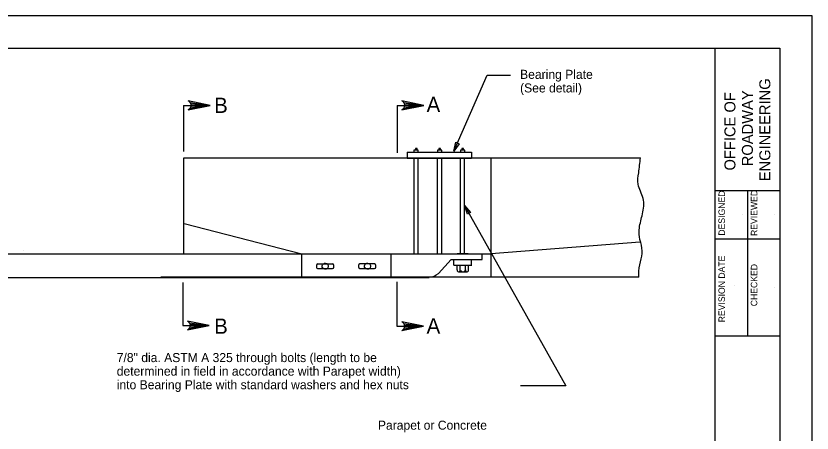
# Model space of a CAD drawing. Extents: x 0 to 34, y 0 to 22.
# Drawn here: x 21.69 to 34, y 15.55 to 22 of the extents above; entities that cross this region are included whole.
import ezdxf

# ---------------------------------------------------------------- set-up
doc = ezdxf.new("R2010")
doc.units = 0
for name, color, linetype in [('SH_Border', 7, 'Continuous'), ('SH_Cut_Line', 7, 'Continuous'), ('SH_Data', 7, 'Continuous'), ('ST_Details', 7, 'Continuous'), ('ST_Text', 7, 'Continuous')]:
    doc.layers.add(name, color=color, linetype=linetype)

msp = doc.modelspace()

# ---------------------------------------------------------------- linework, layer by layer
at = {"layer": 'SH_Border'}
for p, q in [((32.5, 0.5), (32.5, 21.5)), ((32.5, 19.3), (33.5, 19.3)), ((33, 19.3), (33, 17.05)), ((32.5, 18.55), (33.5, 18.55)), ((32.5, 17.05), (33.5, 17.05))]:
    msp.add_line(p, q, dxfattribs=at)
msp.add_lwpolyline([(2, 21.5), (33.5, 21.5), (33.5, 0.5), (2, 0.5)], close=True, dxfattribs=at)
at = {"layer": 'SH_Cut_Line'}
msp.add_lwpolyline([(0, 0), (34, 0), (34, 22), (0, 22)], close=True, dxfattribs=at)
at = {"layer": 'SH_Data'}
for p, q in [((32.92, 18.929), (32.92, 18.929)), ((33.42, 18.929), (33.42, 18.929)), ((32.807, 17.828), (32.807, 17.828)), ((33.42, 17.804), (33.42, 17.804))]:
    msp.add_line(p, q, dxfattribs=at)
at = {"layer": 'ST_Details'}
for p, q in [((27.741, 19.891), (28.734, 19.891)), ((27.741, 19.891), (27.741, 19.801)), ((28.734, 19.891), (28.734, 19.801)), ((24.289, 19.804), (31.346, 19.804)), ((24.289, 18.319), (24.289, 19.804)), ((27.741, 19.801), (28.734, 19.801)), ((27.847, 18.319), (27.847, 19.801)), ((27.912, 18.319), (27.912, 19.801)), ((28.211, 18.319), (28.211, 19.801)), ((28.275, 18.319), (28.275, 19.801)), ((28.563, 18.319), (28.563, 19.801)), ((28.628, 18.319), (28.628, 19.801)), ((29.04, 17.957), (29.04, 19.804)), ((24.291, 18.787), (26.112, 18.319)), ((31.336, 18.498), (29.04, 18.319)), ((19.584, 18.319), (28.9, 18.319)), ((23.37, 18.319), (29.04, 18.319)), ((26.112, 17.959), (26.112, 18.319)), ((27.494, 17.957), (27.494, 18.319)), ((28.223, 18.014), (28.421, 18.23)), ((28.421, 18.23), (28.9, 18.23)), ((28.461, 18.144), (28.461, 18.229)), ((28.683, 18.319), (28.513, 18.319)), ((28.737, 18.143), (28.737, 18.228)), ((28.9, 18.23), (28.9, 18.319)), ((26.339, 18.14), (26.339, 18.114)), ((26.361, 18.162), (26.587, 18.162)), ((26.608, 18.114), (26.608, 18.14)), ((26.989, 18.139), (26.989, 18.114)), ((27.237, 18.162), (27.011, 18.162)), ((27.258, 18.114), (27.258, 18.139)), ((28.461, 18.142), (28.738, 18.142)), ((28.513, 18.069), (28.513, 18.141)), ((28.562, 18.067), (28.562, 18.141)), ((28.64, 18.07), (28.64, 18.138)), ((28.691, 18.07), (28.691, 18.143)), ((26.361, 18.091), (26.587, 18.091)), ((27.011, 18.091), (27.237, 18.091)), ((28.536, 18.039), (28.668, 18.039)), ((19.584, 17.955), (28.08, 17.955))]:
    msp.add_line(p, q, dxfattribs=at)
for points in [[(27.894, 19.92), (27.894, 19.948), (27.869, 19.948), (27.869, 19.92)], [(28.254, 19.92), (28.254, 19.948), (28.23, 19.948), (28.23, 19.92)], [(28.611, 19.921), (28.611, 19.949), (28.586, 19.949), (28.586, 19.921)], [(27.912, 19.891), (27.912, 19.921), (27.845, 19.921), (27.845, 19.891)], [(28.275, 19.891), (28.275, 19.921), (28.209, 19.921), (28.209, 19.891)], [(28.63, 19.891), (28.63, 19.922), (28.563, 19.922), (28.563, 19.891)], [(31.322, 17.957), (29.039, 17.957), (28.056, 17.957), (23.932, 17.957)]]:
    msp.add_lwpolyline(points, dxfattribs=at)
for centre, major_axis, start_param, end_param in [((21.265, 18.993), (0, 0.849), 3.895833, 3.896068), ((21.269, 18.932), (0, 0.849), 3.899262, 3.900648), ((26.361, 18.14), (0, 0.0228), 0, 1.570796), ((26.361, 18.114), (0, 0.0228), 1.570796, 3.141593), ((26.587, 18.14), (0, 0.0228), 4.712389, 6.283185), ((26.587, 18.114), (0, -0.0228), 0, 1.570796), ((27.011, 18.14), (0, 0.0228), 0, 1.570796), ((27.011, 18.114), (0, 0.0228), 1.570796, 3.141593), ((27.237, 18.14), (0, 0.0228), 4.712389, 6.283185), ((27.237, 18.114), (0, -0.0228), 0, 1.570796), ((28.059, 18.24), (0, -0.285), 0.080888, 0.65782), ((28.537, 18.067), (0, 0.0266), 1.488236, 4.755612), ((28.602, 18.084), (0, -0.0433), 5.077454, 7.489005), ((28.665, 18.067), (0, 0.0266), 1.488236, 4.755612)]:
    msp.add_ellipse(centre, major_axis=major_axis, ratio=0.944544, start_param=start_param, end_param=end_param, dxfattribs=at)
for centre in [(26.474, 18.127), (27.128, 18.127)]:
    msp.add_ellipse(centre, major_axis=(0.0055, 0.0478), ratio=0.977529, dxfattribs=at)
msp.add_spline([(31.324, 17.957), (31.32, 18.053), (31.36, 18.24), (31.37, 18.407), (31.33, 18.584), (31.33, 18.719), (31.379, 18.937), (31.389, 19.177), (31.311, 19.395), (31.32, 19.572), (31.346, 19.804)], degree=3, dxfattribs=at)
at = {"layer": 'ST_Text'}
for p, q in [((28.463, 19.905), (28.975, 21.083)), ((28.975, 21.083), (29.338, 21.083)), ((24.282, 20.616), (24.282, 19.904)), ((24.282, 20.616), (24.693, 20.616)), ((24.385, 20.569), (24.693, 20.616)), ((24.388, 20.659), (24.693, 20.616)), ((24.397, 20.589), (24.693, 20.616)), ((24.399, 20.638), (24.693, 20.616)), ((24.402, 20.616), (24.693, 20.616)), ((27.584, 20.616), (27.584, 19.883)), ((27.584, 20.616), (27.996, 20.616)), ((27.687, 20.569), (27.996, 20.616)), ((27.691, 20.659), (27.996, 20.616)), ((27.699, 20.589), (27.996, 20.616)), ((27.701, 20.638), (27.996, 20.616)), ((27.704, 20.616), (27.996, 20.616)), ((24.27, 17.876), (24.27, 17.209)), ((27.582, 17.886), (27.582, 17.199)), ((24.376, 17.252), (24.681, 17.209)), ((27.688, 17.242), (27.993, 17.199)), ((24.27, 17.209), (24.681, 17.209)), ((24.373, 17.162), (24.681, 17.209)), ((24.384, 17.182), (24.681, 17.209)), ((24.387, 17.231), (24.681, 17.209)), ((24.39, 17.209), (24.681, 17.209)), ((27.582, 17.199), (27.993, 17.199)), ((27.685, 17.152), (27.993, 17.199)), ((27.697, 17.172), (27.993, 17.199)), ((27.699, 17.22), (27.993, 17.199)), ((27.702, 17.199), (27.993, 17.199))]:
    msp.add_line(p, q, dxfattribs=at)
for points in [[(24.357, 20.549), (24.693, 20.616), (24.357, 20.684)], [(27.659, 20.549), (27.996, 20.616), (27.659, 20.684)], [(28.628, 19.067), (30.195, 16.275), (29.493, 16.275)], [(24.344, 17.142), (24.681, 17.209), (24.344, 17.276)], [(27.657, 17.132), (27.993, 17.199), (27.657, 17.266)]]:
    msp.add_lwpolyline(points, dxfattribs=at)
for points in [[(28.494, 20.045), (28.545, 20.023), (28.463, 19.905)], [(28.721, 18.959), (28.672, 18.931), (28.628, 19.067)]]:
    msp.add_lwpolyline(points, close=True, dxfattribs=at)
for centre in [(24.33, 20.617), (27.632, 20.617), (24.317, 17.209), (27.629, 17.199)]:
    msp.add_arc(centre, 0.0726, 292.0861, 67.9122, dxfattribs=at)

# ---------------------------------------------------------------- texts
at = {"layer": 'SH_Data'}
for s, height, p in [('ENGINEERING', 0.17, (33.355, 19.442)), ('OFFICE OF', 0.17, (32.815, 19.608)), ('ROADWAY', 0.17, (33.085, 19.674)), ('DESIGNED', 0.1, (32.653, 18.6)), ('REVIEWED', 0.1, (33.153, 18.595)), ('REVISION DATE', 0.1, (32.653, 17.259)), ('CHECKED', 0.1, (33.153, 17.508))]:
    msp.add_text(s, height=height, rotation=90, dxfattribs=at).set_placement(p)
at = {"layer": 'ST_Text'}
for s, height, p in [('Bearing Plate', 0.14, (29.486, 21.026)), ('(See detail)', 0.14, (29.486, 20.816)), ('B', 0.236, (24.757, 20.499)), ('A', 0.236, (28.041, 20.512)), ('B', 0.236, (24.757, 17.082)), ('A', 0.236, (28.041, 17.086)), ('7/8" dia. ASTM A 325 through bolts (length to be', 0.14, (23.251, 16.644)), ('determined in field in accordance with Parapet width)', 0.14, (23.251, 16.434)), ('into Bearing Plate with standard washers and hex nuts', 0.14, (23.251, 16.224)), ('Parapet or Concrete', 0.14, (27.288, 15.598))]:
    msp.add_text(s, height=height, dxfattribs=at).set_placement(p)

doc.saveas('drawing.dxf')
